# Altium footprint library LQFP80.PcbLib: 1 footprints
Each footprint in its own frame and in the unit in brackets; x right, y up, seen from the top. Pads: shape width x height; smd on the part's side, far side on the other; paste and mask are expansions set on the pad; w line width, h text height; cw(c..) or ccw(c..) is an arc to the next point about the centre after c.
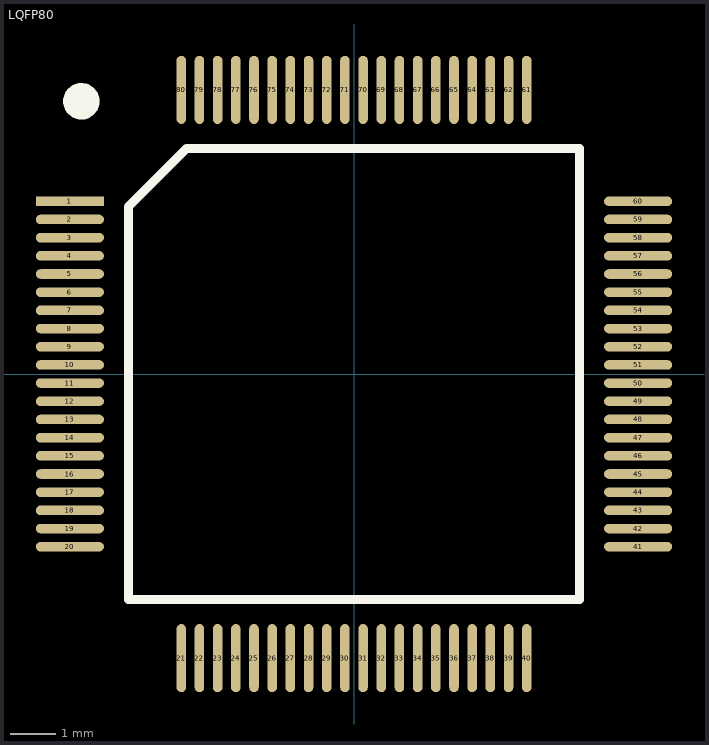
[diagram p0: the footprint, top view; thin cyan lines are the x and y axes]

## LQFP80 [mm]
pads (80):
  rect 1.5x0.21 smd: 1(-6.25,3.8)
  oval 1.5x0.21 smd: 2(-6.25,3.4) 3(-6.25,3) 4(-6.25,2.6) 5(-6.25,2.2) 6(-6.25,1.8) 7(-6.25,1.4) 8(-6.25,1) 9(-6.25,0.6) 10(-6.25,0.2) 11(-6.25,-0.2) 12(-6.25,-0.6) 13(-6.25,-1) 14(-6.25,-1.4) 15(-6.25,-1.8) 16(-6.25,-2.2) 17(-6.25,-2.6) 18(-6.25,-3) 19(-6.25,-3.4) 20(-6.25,-3.8) 41(6.25,-3.8) 42(6.25,-3.4) 43(6.25,-3) 44(6.25,-2.6) 45(6.25,-2.2) 46(6.25,-1.8) 47(6.25,-1.4) 48(6.25,-1) 49(6.25,-0.6) 50(6.25,-0.2) 51(6.25,0.2) 52(6.25,0.6) 53(6.25,1) 54(6.25,1.4) 55(6.25,1.8) 56(6.25,2.2) 57(6.25,2.6) 58(6.25,3) 59(6.25,3.4) 60(6.25,3.8)
  oval 0.21x1.5 smd: 21(-3.8,-6.25) 22(-3.4,-6.25) 23(-3,-6.25) 24(-2.6,-6.25) 25(-2.2,-6.25) 26(-1.8,-6.25) 27(-1.4,-6.25) 28(-1,-6.25) 29(-0.6,-6.25) 30(-0.2,-6.25) 31(0.2,-6.25) 32(0.6,-6.25) 33(1,-6.25) 34(1.4,-6.25) 35(1.8,-6.25) 36(2.2,-6.25) 37(2.6,-6.25) 38(3,-6.25) 39(3.4,-6.25) 40(3.8,-6.25) 61(3.8,6.25) 62(3.4,6.25) 63(3,6.25) 64(2.6,6.25) 65(2.2,6.25) 66(1.8,6.25) 67(1.4,6.25) 68(1,6.25) 69(0.6,6.25) 70(0.2,6.25) 71(-0.2,6.25) 72(-0.6,6.25) 73(-1,6.25) 74(-1.4,6.25) 75(-1.8,6.25) 76(-2.2,6.25) 77(-2.6,6.25) 78(-3,6.25) 79(-3.4,6.25) 80(-3.8,6.25)
Top Overlay:
  circle w0.4: c-6,6 r0.2
  lines w0.2: -4.965,-4.965 4.965,-4.965 4.965,4.965 -3.68,4.965 -4.965,3.68 -4.965,-4.965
